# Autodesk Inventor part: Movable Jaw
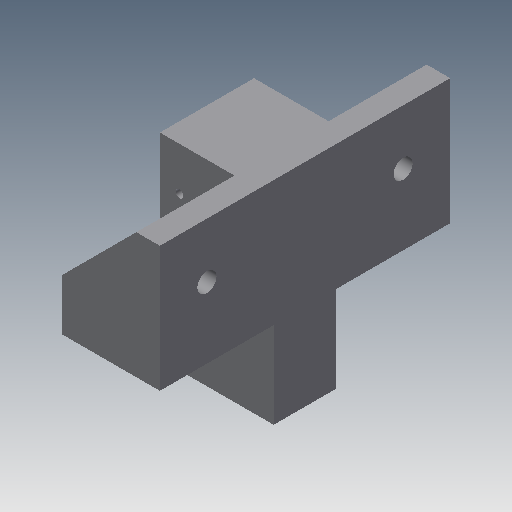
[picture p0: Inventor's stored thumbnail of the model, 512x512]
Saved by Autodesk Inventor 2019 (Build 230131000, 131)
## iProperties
Shininess: 77.0
Length Units: 11269
Angle Units: 11279
Time Units: 11290
Mass Units: 11283
Length Display Precision: 3
Angle Display Precision: 2
Created: 2002-02
Part Number: Movable Jaw
Document SubType Name: Modeling
Designer: ***
Density: 1 g/cm^3
Material: Generic
Mass: 56.5588 g
Surface Area: 124.299 cm^2
Volume: 56.5588 cm^3
Appearance: Default
Density: 0.0
Volumn: 0.0
Area: 0.0
PropertySet Name: Model Information
Control State: 0
Master: False
Checked Out: False
Author: ***
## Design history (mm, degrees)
sketch "Sketch2"
  geometry: L1 (2.39, 41.509)-(2.39, 9.509); L2 (2.39, 9.509)-(-22.61, 9.509); L3 (-22.61, 9.509)-(-22.61, 22.509); L4 (-22.61, 22.509)-(-3.61, 41.509); L5 (-3.61, 41.509)-(2.39, 41.509)
  constraints: 10 end point, 2 parallel, 1 perpendicular, 1 vertical
  dimensions: "d0" = 25 distance of L1.end L2.end; "d2" = 13 distance of L2.end L3.end; "d3" = 32 distance between parallel lines of L5 L2; "d4" = 6 distance of L4.end L1.start
extrude "Extrusion1" new body sketch "Sketch2" stored distance "d5" = 74; taper "d6" = 0 deg
sketch "Sketch3"
  geometry: L1 (-19, 25)-(11, 25); L2 (11, 25)-(11, 49); L3 (11, 49)-(-19, 49); L4 (-19, 49)-(-19, 25); L5 (0, 0)-(13, 0) reference; L6 (-19, 74)-(-19, 0) reference; L7 (11.924, 29)-(35, 29); L8 (35, 29)-(35, 45); L9 (35, 45)-(11.924, 45); L10 (11.924, 45)-(11.924, 29); L11 (13, 74)-(13, 0) reference
  constraints: 16 end point, 4 parallel, 2 horizontal, 2 perpendicular, 1 collinear
  dimensions: "d7" = 24 distance of L3.end L1.start; "d8" = 30 distance of L1.start L1.end; "d9" = 25 distance between parallel lines of L5 L1; "d10" = 16 distance of L7.end L8.end; "d11" = 4 distance between parallel lines of L3 L9; "d12" = 22 distance between parallel lines of L11 L8
extrude "Extrusion2" join sketch "Sketch3" distance "d13" = 25; taper "d14" = 0 deg
sketch "Sketch4"
  geometry: L1 (-19, -25)-(-19, -49) reference; L2 (-19, -49)-(0, -49) reference; 1 further point
  dimensions: "d15" = 11 distance from line of L1 point (-8, -37); "d16" = 12 distance from line of L2 point (-8, -37)
hole "Hole1" sketch "Sketch4" at (-8, -37) diameter "d17" = 10; stored, may be unused: countersink angle "d21" = 82 deg, drill point angle "d23" = 0 deg; dims "d18" = 6, "d19" = 4, "d20" = 2, "d22" = 13
sketch "Sketch5"
  geometry: L1 (-19, -49)-(-19, -74) reference; L2 (0, -74)-(13, -74) reference; 1 further point
  dimensions: "d24" = 14 distance from line of L1 point (-5, -62); "d25" = 12 distance from line of L2 point (-5, -62)
hole "Hole2" sketch "Sketch5" at (-5, -62) diameter "d26" = 4.917; stored, may be unused: countersink angle "d30" = 82 deg, drill point angle "d32" = 0 deg; dims "d27" = 12, "d28" = 8, "d29" = 10, "d31" = 17.1
mirror "Mirror1"
sketch "Sketch6"
  geometry: L1 (0, 19)-(0, 0) reference; 1 further point
  dimensions: "d33" = 5 distance from line of L1 point (-5, 8); "d34" = 11 vertical distance of L1.start point (-5, 8)
hole "Hole3" sketch "Sketch6" at (-5, 8) diameter "d35" = 2; stored, may be unused: countersink angle "d39" = 82 deg, drill point angle "d41" = 0 deg; dims "d36" = 6, "d37" = 8, "d38" = 10, "d40" = 13
body "Solid1"
